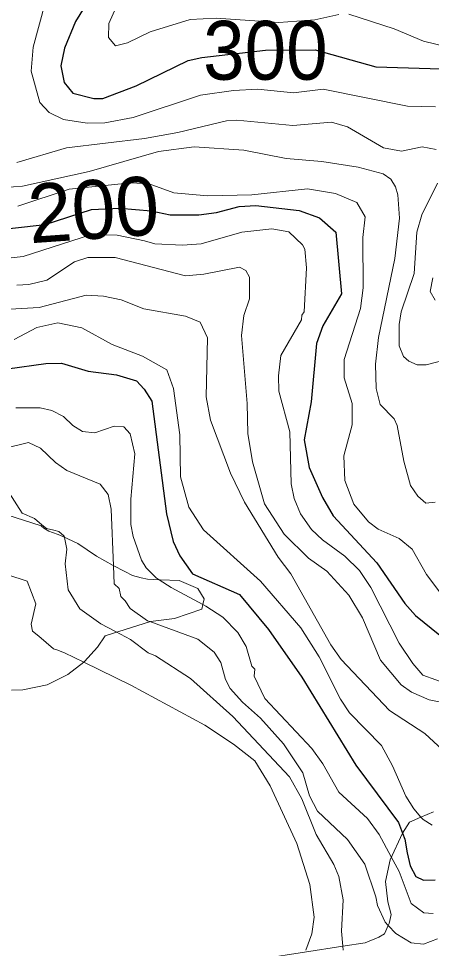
# Model space of a CAD drawing. Extents: x 474.5 to 500, y 7345.7 to 7373.4.
# Drawn here: x 484.682 to 485.244, y 7365.995 to 7367.259 of the extents above; entities that cross this region are included whole.
import ezdxf
from ezdxf.enums import TextEntityAlignment as Align

# ---------------------------------------------------------------- set-up
doc = ezdxf.new("R2010")
doc.units = 0
doc.header["$LTSCALE"] = 0.032
doc.linetypes.add('SHORT_DASHED', pattern=[2.7, 1.5, -1.2])
for name, color, linetype, lineweight in [('1', 7, 'Continuous', 25), ('16', 7, 'SHORT_DASHED', 13), ('2', 7, 'Continuous', 13)]:
    doc.layers.add(name, color=color, linetype=linetype, lineweight=lineweight)
doc.layers.add('61', color=7, linetype='Continuous')

msp = doc.modelspace()

# ---------------------------------------------------------------- linework, layer by layer
at = {"layer": '1'}
for points in [[(484.8022, 7367.3248), (484.7597, 7367.2556), (484.7447, 7367.2194), (484.7399, 7367.1952), (484.7442, 7367.1724), (484.7559, 7367.1578), (484.7847, 7367.1509), (484.797, 7367.1507), (484.8421, 7367.1678), (484.9132, 7367.2025), (484.9318, 7367.2064), (485.0182, 7367.2163), (485.0861, 7367.2171), (485.1685, 7367.1936), (485.3015, 7367.1897)], [(484.6292, 7366.9693), (484.7182, 7366.9794), (484.7814, 7366.9996), (484.82, 7367.0015), (484.8628, 7366.9979), (484.8887, 7366.9927), (484.9274, 7366.9927), (484.9516, 7366.9957), (484.9827, 7367.0039), (485.005, 7367.0053), (485.0643, 7366.9985), (485.0919, 7366.9885), (485.1141, 7366.9689), (485.1219, 7366.885), (485.0963, 7366.8416), (485.0877, 7366.8177), (485.0805, 7366.7383), (485.0711, 7366.6867), (485.0776, 7366.6489), (485.0961, 7366.608), (485.1105, 7366.583), (485.1697, 7366.519), (485.208, 7366.464), (485.2226, 7366.4477), (485.2555, 7366.421)], [(484.6672, 7366.7832), (484.7193, 7366.7905), (484.7406, 7366.7907), (484.777, 7366.7797), (484.8156, 7366.7748), (484.8429, 7366.7666), (484.8533, 7366.7554), (484.8635, 7366.7389), (484.8834, 7366.5857), (484.8928, 7366.5481), (484.9017, 7366.5286), (484.9189, 7366.5042), (484.9828, 7366.476), (485.0224, 7366.4284), (485.0679, 7366.3637), (485.1413, 7366.2441), (485.1993, 7366.1661), (485.205, 7366.1516), (485.2082, 7366.1435), (485.2113, 7366.125), (485.2152, 7366.107), (485.2228, 7366.0927), (485.2334, 7366.0876), (485.2492, 7366.0883)]]:
    msp.add_lwpolyline(points, dxfattribs=at)
at = {"layer": '16'}
for points in [[(484.713, 7366.5694), (484.6504, 7366.5891), (484.6019, 7366.6004), (484.5823, 7366.6035), (484.5463, 7366.6014), (484.5331, 7366.5945)], [(484.7425, 7366.5551), (484.736, 7366.5576), (484.7284, 7366.5606), (484.7234, 7366.5621), (484.7167, 7366.5664), (484.713, 7366.5694)], [(484.8111, 7366.5154), (484.7885, 7366.5282), (484.7628, 7366.5457), (484.7425, 7366.5551)], [(484.8749, 7366.496), (484.8578, 7366.4971), (484.849, 7366.4987), (484.8372, 7366.502), (484.8268, 7366.5075), (484.8111, 7366.5154)], [(484.9332, 7366.4624), (484.9349, 7366.4704), (484.9261, 7366.4843), (484.9009, 7366.4952), (484.8749, 7366.496)], [(484.8618, 7366.4395), (484.8947, 7366.4436), (484.9318, 7366.456), (484.9332, 7366.4624)], [(484.771, 7366.3841), (484.772, 7366.3848), (484.7896, 7366.4044), (484.7999, 7366.4199), (484.8618, 7366.4395)], [(484.6728, 7366.3462), (484.6881, 7366.3465), (484.7212, 7366.3532), (484.7494, 7366.3673), (484.771, 7366.3841)], [(485.247, 7366.1807), (485.23, 7366.1734), (485.2144, 7366.1667), (485.205, 7366.1516), (485.188, 7366.1155), (485.1818, 7366.086), (485.1849, 7366.058), (485.1896, 7366.041)], [(485.1896, 7366.041), (485.1865, 7366.0285), (485.1854, 7366.026), (485.1803, 7366.0146), (485.1725, 7366.0099), (485.1539, 7366.0025), (485.1238, 7365.9979), (485.0714, 7365.9898), (485.0127, 7365.9808)]]:
    msp.add_lwpolyline(points, dxfattribs=at)
at = {"layer": '2'}
for points in [[(484.718, 7367.2788), (484.7023, 7367.2205), (484.6992, 7367.1878), (484.7112, 7367.1454), (484.724, 7367.1318), (484.7432, 7367.1221), (484.7756, 7367.1171), (484.7995, 7367.1178), (484.8383, 7367.1251), (484.93, 7367.1552), (484.9746, 7367.1617), (485.0077, 7367.1633), (485.0563, 7367.1586), (485.0967, 7367.1633), (485.2116, 7367.1401), (485.2498, 7367.1394)], [(484.8188, 7367.2829), (484.8053, 7367.2529), (484.8045, 7367.2338), (484.8143, 7367.2225), (484.8306, 7367.2266), (484.8613, 7367.2413), (484.9159, 7367.2582), (484.9514, 7367.2599), (485.0363, 7367.2543), (485.0856, 7367.2578), (485.1181, 7367.2649)], [(485.132, 7367.2656), (485.1936, 7367.2456), (485.2334, 7367.2288), (485.2654, 7367.2208), (485.3115, 7367.2159), (485.4079, 7367.22), (485.4265, 7367.2263), (485.4417, 7367.2492), (485.4474, 7367.2652)], [(484.6797, 7367.0636), (484.7473, 7367.0836), (484.8536, 7367.0963), (484.8989, 7367.1043), (484.9654, 7367.1202), (484.9793, 7367.1211), (485.0556, 7367.1139), (485.1084, 7367.1186), (485.1302, 7367.1121), (485.1789, 7367.0838), (485.2034, 7367.0789), (485.2315, 7367.085), (485.2507, 7367.0813)], [(484.6504, 7367.0286), (484.6876, 7367.0313), (484.7782, 7367.0516), (484.8729, 7367.0787), (484.9214, 7367.0852), (484.989, 7367.0804), (485.0465, 7367.0692), (485.0951, 7367.0652), (485.1446, 7367.0572), (485.1784, 7367.0481), (485.1891, 7367.041), (485.1953, 7367.0307), (485.1985, 7367.0197), (485.2009, 7366.9878), (485.1945, 7366.9333), (485.1721, 7366.8257), (485.1683, 7366.7893), (485.1692, 7366.7563), (485.1743, 7366.7345), (485.1935, 7366.7151), (485.1977, 7366.706), (485.2066, 7366.6573), (485.2159, 7366.6246), (485.2258, 7366.6097), (485.2364, 7366.6002), (485.2493, 7366.6017)], [(484.6814, 7367.0045), (484.7509, 7367.0272), (484.8351, 7367.0358), (484.8598, 7367.0345), (484.8937, 7367.0226), (484.9392, 7367.0182), (484.9997, 7367.0198), (485.0757, 7367.0277), (485.1135, 7367.0215), (485.1427, 7367.0094), (485.1538, 7366.9897), (485.1508, 7366.9617), (485.1515, 7366.8932), (485.1475, 7366.8649), (485.1255, 7366.7959), (485.1256, 7366.7708), (485.1363, 7366.7357), (485.1363, 7366.7071), (485.125, 7366.6646), (485.1265, 7366.6313), (485.1386, 7366.5988), (485.1584, 7366.5748), (485.1717, 7366.5649), (485.2003, 7366.5521), (485.2181, 7366.5376), (485.2374, 7366.5035), (485.268, 7366.4631)], [(485.2527, 7367.0355), (485.2311, 7366.9926), (485.2242, 7366.9689), (485.2209, 7366.9129), (485.2031, 7366.8608), (485.2002, 7366.8432), (485.2002, 7366.8142), (485.2062, 7366.7999), (485.2136, 7366.7933), (485.2247, 7366.7887), (485.237, 7366.7884), (485.2671, 7366.7963)], [(484.6311, 7366.9296), (484.6883, 7366.936), (484.7802, 7366.9652), (484.8166, 7366.9647), (484.8538, 7366.9571), (484.8675, 7366.953), (484.9055, 7366.9512), (484.9306, 7366.9529), (484.9863, 7366.969), (485.0269, 7366.9735), (485.0499, 7366.9695), (485.0685, 7366.9519), (485.0717, 7366.9456), (485.0742, 7366.9202), (485.0709, 7366.8605), (485.0678, 7366.8559), (485.0675, 7366.8498), (485.0392, 7366.8014), (485.0359, 7366.7734), (485.0367, 7366.7526), (485.0517, 7366.6974), (485.0535, 7366.6268), (485.0572, 7366.6065)], [(484.6798, 7366.8969), (484.696, 7366.8976), (484.7208, 7366.9036), (484.7583, 7366.9287), (484.7767, 7366.9344), (484.8138, 7366.9344), (484.9096, 7366.9097), (484.9344, 7366.9118), (484.983, 7366.9215), (484.9916, 7366.9168), (484.9967, 7366.9078), (484.9965, 7366.8784), (484.9888, 7366.8557), (484.9855, 7366.8286), (484.9935, 7366.736), (484.9944, 7366.6949), (485.0005, 7366.6568), (485.0169, 7366.5996), (485.0436, 7366.558), (485.0767, 7366.5257), (485.1018, 7366.5077), (485.1319, 7366.4752), (485.1505, 7366.4443), (485.1751, 7366.3869), (485.2029, 7366.3533), (485.2172, 7366.3435), (485.2411, 7366.333), (485.2893, 7366.3233)], [(485.2461, 7366.9069), (485.2425, 7366.8884), (485.2495, 7366.8765)], [(484.6383, 7366.8625), (484.7101, 7366.8665), (484.7741, 7366.8833), (484.7979, 7366.8818), (484.8218, 7366.877), (484.8526, 7366.8645), (484.9096, 7366.8547), (484.9295, 7366.8467), (484.9393, 7366.825), (484.9378, 7366.7448), (484.9433, 7366.7132), (484.9707, 7366.6411), (484.9897, 7366.6015), (485.0357, 7366.527), (485.0527, 7366.5041), (485.1073, 7366.4076), (485.1213, 7366.3878), (485.1873, 7366.3185), (485.2352, 7366.2873), (485.2712, 7366.2539)], [(484.6762, 7366.8231), (484.7071, 7366.8394), (484.7356, 7366.8458), (484.7685, 7366.839), (484.8097, 7366.8161), (484.851, 7366.8002), (484.8839, 7366.7817), (484.8931, 7366.7562), (484.9018, 7366.6932), (484.9027, 7366.6363), (484.914, 7366.595), (484.9339, 7366.5641), (485.0116, 7366.4944), (485.0663, 7366.4307), (485.0915, 7366.3913), (485.1203, 7366.3339), (485.1325, 7366.3154), (485.1762, 7366.2706), (485.1911, 7366.2433), (485.2094, 7366.2019), (485.2203, 7366.1845), (485.23, 7366.1734), (485.2328, 7366.1702), (485.2452, 7366.1623)], [(484.6787, 7366.7302), (484.7117, 7366.7302)], [(484.7117, 7366.7302), (484.7277, 7366.7262), (484.7433, 7366.7184), (484.7561, 7366.7061), (484.7691, 7366.6977), (484.7861, 7366.6959), (484.8122, 7366.7053), (484.8255, 7366.7043), (484.8342, 7366.6945), (484.8403, 7366.6674), (484.8349, 7366.6059), (484.8349, 7366.5712), (484.838, 7366.5552), (484.8494, 7366.523), (484.856, 7366.5126), (484.8694, 7366.4989), (484.8738, 7366.496), (484.8901, 7366.4855), (484.9332, 7366.4624), (484.9372, 7366.4603), (484.9603, 7366.4452), (484.9809, 7366.4244), (484.9921, 7366.4056), (484.9998, 7366.3788), (485.0037, 7366.3745), (485.003, 7366.3652), (485.0176, 7366.3345), (485.0813, 7366.2665), (485.0966, 7366.2457), (485.1182, 7366.2075), (485.1574, 7366.1714), (485.1732, 7366.1499), (485.1896, 7366.1194), (485.2003, 7366.0995), (485.2165, 7366.0557), (485.2337, 7366.0431), (485.2465, 7366.0421)], [(484.6646, 7366.6751), (484.6956, 7366.683), (484.712, 7366.6751), (484.7324, 7366.6555), (484.7478, 7366.6447), (484.7933, 7366.6264), (484.8044, 7366.612), (484.8084, 7366.5924), (484.8114, 7366.5152), (484.8124, 7366.4907), (484.8192, 7366.4841), (484.8213, 7366.4736), (484.8271, 7366.4677), (484.8343, 7366.4573), (484.8576, 7366.4404), (484.8607, 7366.4393), (484.9263, 7366.4155), (484.9486, 7366.3976), (484.9576, 7366.3836), (484.9637, 7366.3607), (484.9703, 7366.3482), (484.9869, 7366.3298), (485.0115, 7366.3078), (485.0429, 7366.2732), (485.0692, 7366.2338), (485.0784, 7366.2022), (485.0891, 7366.1816), (485.1301, 7366.1428), (485.1536, 7366.1093), (485.1687, 7366.065), (485.1706, 7366.0531), (485.1811, 7366.0306), (485.1854, 7366.026), (485.1957, 7366.0149), (485.2167, 7366.0025), (485.2334, 7366.0007), (485.2523, 7366.0078)], [(484.6696, 7366.6144), (484.6873, 7366.5867), (484.7039, 7366.5793), (484.7138, 7366.5711), (484.7201, 7366.5659), (484.7304, 7366.5635), (484.737, 7366.562), (484.7438, 7366.5561), (484.7441, 7366.5559), (484.7478, 7366.5379), (484.7455, 7366.5178), (484.7497, 7366.4824), (484.7654, 7366.4565), (484.794, 7366.4362), (484.8143, 7366.4257), (484.8348, 7366.415), (484.8585, 7366.3968), (484.8685, 7366.3926), (484.9164, 7366.3621), (484.974, 7366.3102), (485.0511, 7366.2281), (485.0676, 7366.1983), (485.0871, 7366.1496), (485.1115, 7366.1089), (485.1181, 7366.0925), (485.1243, 7366.0611), (485.122, 7366.0184), (485.1238, 7365.9979), (485.1243, 7365.9925)], [(485.0572, 7366.6065), (485.066, 7366.586), (485.0809, 7366.5647), (485.0958, 7366.5507), (485.1265, 7366.5285), (485.1461, 7366.5089), (485.1617, 7366.4855), (485.2004, 7366.4099), (485.2187, 7366.3824), (485.2327, 7366.3666), (485.2678, 7366.3536)], [(485.0733, 7365.9923), (485.0814, 7366.0148), (485.0845, 7366.0372), (485.0789, 7366.0818), (485.0612, 7366.1377), (485.0245, 7366.2159), (485.0037, 7366.2501), (484.975, 7366.2724), (484.9356, 7366.2984), (484.8351, 7366.3527), (484.771, 7366.3841), (484.7446, 7366.397), (484.7345, 7366.4008), (484.7297, 7366.4022), (484.7096, 7366.4194), (484.7013, 7366.4264), (484.6993, 7366.436), (484.7056, 7366.4635), (484.6937, 7366.4944), (484.6675, 7366.5027), (484.6465, 7366.5059), (484.6341, 7366.5044), (484.6078, 7366.5248), (484.5731, 7366.5769)]]:
    msp.add_lwpolyline(points, dxfattribs=at)

# ---------------------------------------------------------------- texts
at = {"layer": '61', "width": 0.95}
msp.add_text('300', height=0.08, dxfattribs=at).set_placement((485.0182, 7367.1763), align=Align.CENTER)
at = {"layer": '61'}
msp.add_text('200', height=0.08, rotation=4.01, dxfattribs=at).set_placement((484.7869, 7366.96), align=Align.CENTER)

doc.saveas('drawing.dxf')
